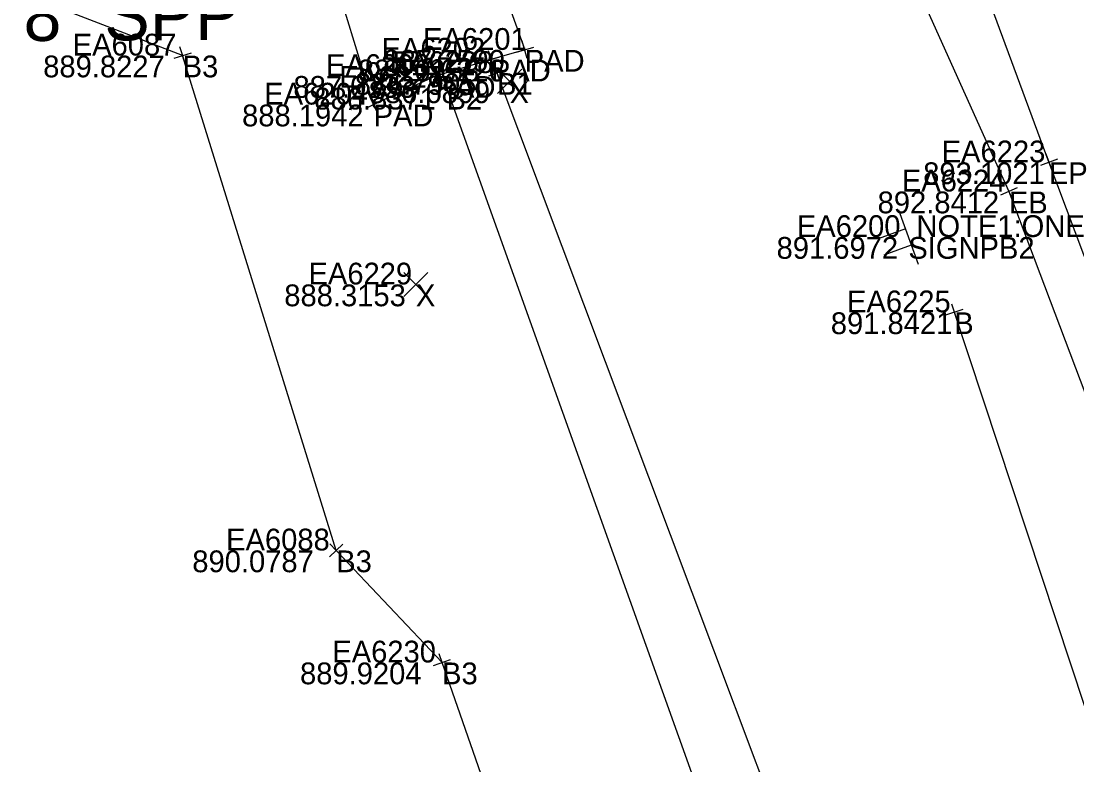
# Model space of a CAD drawing. Extents: x 179044 to 189691, y 286531 to 301257.
# Drawn here: x 180169.6 to 180227.8, y 300512.8 to 300553.8 of the extents above; entities that cross this region are included whole.
import ezdxf

# ---------------------------------------------------------------- set-up
doc = ezdxf.new("R2010")
doc.units = 0
for name, color, linetype in [('DR_X_Text', 7, 'Continuous'), ('PV_X_EOP', 7, 'Continuous'), ('PV_X_Shoulder_Aggregate', 7, 'Continuous'), ('RD_X_Concrete_Pad', 7, 'Continuous'), ('SN_X_Public', 7, 'Continuous'), ('SV_X_Break_Lines', 7, 'Continuous'), ('SV_X_Random_Point', 7, 'Continuous'), ('SV_X_Shot_Marker', 7, 'Continuous'), ('SV_X_Text_Comment', 7, 'Continuous'), ('SV_X_Text_Description', 7, 'Continuous'), ('SV_X_Text_Elevation', 7, 'Continuous'), ('SV_X_Text_Name', 7, 'Continuous')]:
    doc.layers.add(name, color=color, linetype=linetype)

msp = doc.modelspace()

# ---------------------------------------------------------------- linework, layer by layer
at = {"layer": 'PV_X_EOP'}
msp.add_lwpolyline([(179371.146, 300578.051), (179477.168, 300579.528), (179563.012, 300579.455), (179660.626, 300579.907), (179772.349, 300580.843), (179883.302, 300581.216), (179986.953, 300581.659), (180080.461, 300581.624), (180131.142, 300581.875), (180152.421, 300580.897), (180177.372, 300581.245), (180192.481, 300580.813), (180205.116, 300578.916), (180211.895, 300576.366), (180217.061, 300570.924), (180226.256, 300546.032), (180252.64, 300475.662), (180284.891, 300388.784), (180312.046, 300315.753), (180341.998, 300235.308)], dxfattribs=at)
at = {"layer": 'PV_X_Shoulder_Aggregate'}
msp.add_lwpolyline([(179563.451, 300578.229), (179660.977, 300578.016), (179772.748, 300578.901), (179883.7, 300579.446), (179986.895, 300579.719), (180080.262, 300579.655), (180131.517, 300579.632), (180152.892, 300578.404), (180177.169, 300578.87), (180192.854, 300577.824), (180203.732, 300575.396), (180212.869, 300569.272), (180224.05, 300544.426), (180250.422, 300474.503), (180282.665, 300386.992), (180309.922, 300313.986), (180339.844, 300234.334)], dxfattribs=at)
at = {"layer": 'RD_X_Concrete_Pad'}
msp.add_lwpolyline([(180197.385, 300552.231), (180195.522, 300551.693), (180192.478, 300550.79), (180189.063, 300549.217), (180186.577, 300557.315), (180189.052, 300558.338), (180186.77, 300563.783), (180188.444, 300564.199), (180190.647, 300565), (180192.332, 300565.592), (180194.898, 300559.216)], close=True, dxfattribs=at)
at = {"layer": 'SN_X_Public'}
for p, q in [((180217.966, 300543.424), (180219.061, 300540.417)), ((180218.35, 300542.371), (180216.846, 300541.824)), ((180218.514, 300541.92), (180218.514, 300541.92)), ((180218.678, 300541.469), (180217.174, 300540.922))]:
    msp.add_line(p, q, dxfattribs=at)
at = {"layer": 'SV_X_Break_Lines'}
for points in [[(180320.902, 300212.184), (180282.069, 300307.438), (180254.033, 300376.286), (180214.216, 300457.225), (180192.833, 300518.475), (180187.002, 300524.649), (180178.544, 300551.918), (180167.492, 300556.189), (180133.433, 300560.27), (180078.668, 300564.705), (179988.563, 300564.714), (179881.16, 300565.14), (179774.574, 300564.41), (179665.201, 300563.792), (179565.532, 300563.693)], [(180195.858, 300550.954), (180223.235, 300478.014), (180267.79, 300377.03), (180294.707, 300311.679), (180328.37, 300228.858)], [(180193.081, 300550.145), (180219.619, 300475.886), (180264.736, 300375.588), (180291.668, 300310.215), (180324.832, 300229.149)], [(180221.044, 300537.77), (180244.232, 300467.66), (180276.377, 300381.787), (180302.554, 300313.637), (180332.865, 300230.917)]]:
    msp.add_lwpolyline(points, dxfattribs=at)
at = {"layer": 'SV_X_Random_Point'}
for p, q in [((180195.888, 300549.827), (180197.221, 300551.162)), ((180195.888, 300551.162), (180197.221, 300549.827)), ((180190.722, 300538.637), (180192.055, 300539.972)), ((180190.722, 300539.972), (180192.055, 300538.637))]:
    msp.add_line(p, q, dxfattribs=at)
at = {"layer": 'SV_X_Shot_Marker'}
for p, q in [((180197.524, 300551.751), (180197.246, 300552.711)), ((180178.067, 300551.77), (180179.022, 300552.066)), ((180178.692, 300551.441), (180178.396, 300552.396)), ((180195.661, 300551.212), (180195.383, 300552.173)), ((180197.865, 300552.37), (180196.905, 300552.092)), ((180197.385, 300552.231), (180197.385, 300552.231)), ((180178.544, 300551.918), (180178.544, 300551.918)), ((180196.002, 300551.831), (180195.042, 300551.554)), ((180195.522, 300551.693), (180195.522, 300551.693)), ((180195.682, 300551.422), (180196.033, 300550.486)), ((180192.957, 300550.932), (180191.999, 300550.648)), ((180192.62, 300550.311), (180192.336, 300551.269)), ((180196.326, 300551.13), (180195.39, 300550.778)), ((180195.858, 300550.954), (180195.858, 300550.954)), ((180192.478, 300550.79), (180192.478, 300550.79)), ((180193.552, 300550.313), (180192.61, 300549.977)), ((180192.913, 300550.616), (180193.249, 300549.674)), ((180189.273, 300548.763), (180188.854, 300549.671)), ((180193.081, 300550.145), (180193.081, 300550.145)), ((180189.518, 300549.426), (180188.609, 300549.008)), ((180189.063, 300549.217), (180189.063, 300549.217)), ((180226.725, 300546.206), (180225.787, 300545.859)), ((180226.083, 300546.501), (180226.429, 300545.563)), ((180226.256, 300546.032), (180226.256, 300546.032)), ((180224.506, 300544.631), (180223.594, 300544.221)), ((180223.845, 300544.882), (180224.255, 300543.97)), ((180224.05, 300544.426), (180224.05, 300544.426)), ((180220.887, 300538.245), (180221.201, 300537.295)), ((180221.519, 300537.927), (180220.57, 300537.613)), ((180221.044, 300537.77), (180221.044, 300537.77)), ((180186.638, 300524.305), (180187.366, 300524.992)), ((180187.345, 300524.285), (180186.659, 300525.012)), ((180187.002, 300524.649), (180187.002, 300524.649)), ((180192.997, 300518.003), (180192.668, 300518.947)), ((180192.361, 300518.31), (180193.305, 300518.639)), ((180192.833, 300518.475), (180192.833, 300518.475))]:
    msp.add_line(p, q, dxfattribs=at)

# ---------------------------------------------------------------- texts
at = {"layer": 'DR_X_Text'}
msp.add_text('8" SPP', height=2.8, rotation=0.35657, dxfattribs=at).set_placement((180169.784, 300552.718))
at = {"layer": 'SV_X_Text_Comment'}
for s, p in [('PAD', (180197.385, 300551.031)), ('B3', (180178.544, 300550.718)), ('PAD', (180195.522, 300550.493)), ('B1', (180195.858, 300549.754)), ('PAD', (180192.478, 300549.59)), ('X', (180196.554, 300549.295)), ('B2', (180193.081, 300548.945)), ('PAD', (180189.063, 300548.017)), ('EP', (180226.256, 300544.832)), ('EB', (180224.05, 300543.226)), ('SIGNPB2', (180218.514, 300540.72)), ('X', (180191.389, 300538.104)), ('B', (180221.044, 300536.57)), ('B3', (180187.002, 300523.449)), ('B3', (180192.833, 300517.275))]:
    msp.add_text(s, height=1.2, dxfattribs=at).set_placement(p)
at = {"layer": 'SV_X_Text_Description'}
msp.add_text(' NOTE1:ONE WAY', height=1.2, dxfattribs=at).set_placement((180218.514, 300541.92))
at = {"layer": 'SV_X_Text_Elevation'}
for s, p in [('887.7590', (180189.6, 300551.031)), ('889.8227', (180170.863, 300550.718)), ('887.0158', (180188.191, 300550.493)), ('886.7905', (180188.025, 300549.754)), ('887.0333', (180184.646, 300549.59)), ('886.6899', (180188.788, 300549.295)), ('886.8371', (180185.799, 300548.945)), ('888.1942', (180181.817, 300548.017)), ('893.1021', (180219.334, 300544.832)), ('892.8412', (180216.823, 300543.226)), ('891.6972', (180211.258, 300540.72)), ('888.3153', (180184.142, 300538.104)), ('891.8421', (180214.245, 300536.57)), ('890.0787', (180179.075, 300523.449)), ('889.9204', (180185.009, 300517.275))]:
    msp.add_text(s, height=1.2, dxfattribs=at).set_placement(p)
at = {"layer": 'SV_X_Text_Name'}
for s, p in [('EA6087', (180172.488, 300551.918)), ('EA6201', (180191.785, 300552.231)), ('EA6202', (180189.494, 300551.693)), ('EA6203', (180186.441, 300550.79)), ('EA6228', (180189.943, 300550.954)), ('EA6226', (180190.574, 300550.495)), ('EA6227', (180187.176, 300550.145)), ('EA6204', (180183.036, 300549.217)), ('EA6223', (180220.351, 300546.032)), ('EA6224', (180218.155, 300544.426)), ('EA6200', (180212.372, 300541.92)), ('EA6229', (180185.474, 300539.304)), ('EA6225', (180215.139, 300537.77)), ('EA6088', (180180.936, 300524.649)), ('EA6230', (180186.786, 300518.475))]:
    msp.add_text(s, height=1.2, dxfattribs=at).set_placement(p)

doc.saveas('drawing.dxf')
